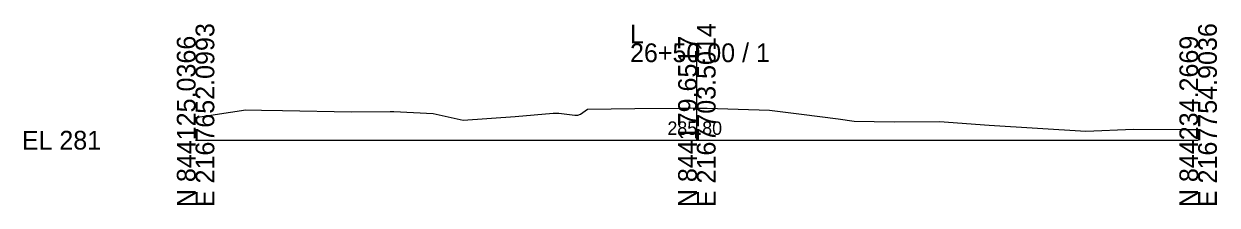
# Model space of a CAD drawing. Extents: x -26 to 1153, y -10 to 9544.
# Drawn here: x 974.3 to 1152.8, y 7990.3 to 8017.4 of the extents above; entities that cross this region are included whole.
import ezdxf

# ---------------------------------------------------------------- set-up
doc = ezdxf.new("R2010")
doc.units = 0
for name, color, linetype in [('Default', 7, 'Continuous'), ('Exist Cross Section Cell', 7, 'Continuous'), ('Exist XS Center Line Elevation Label', 7, 'Continuous'), ('Prop XS Earthwork Shape', 7, 'Continuous')]:
    doc.layers.add(name, color=color, linetype=linetype)

msp = doc.modelspace()

# ---------------------------------------------------------------- linework, layer by layer
at = {"layer": 'Exist Cross Section Cell'}
for p, q in [((1075, 8000), (1075, 8014.46)), ((1000, 8000), (1075, 8000)), ((1075, 8000), (1150, 8000))]:
    msp.add_line(p, q, dxfattribs=at)
at = {"layer": 'Prop XS Earthwork Shape'}
for p, q in [((1000, 8003.39), (1007.5, 8004.52)), ((1007.5, 8004.52), (1009.87, 8004.48)), ((1009.87, 8004.48), (1012.99, 8004.46)), ((1012.99, 8004.46), (1023.34, 8004.25)), ((1023.34, 8004.25), (1029.13, 8004.27)), ((1029.13, 8004.27), (1029.68, 8004.29)), ((1029.68, 8004.29), (1035.57, 8004.01)), ((1035.57, 8004.01), (1040.05, 8002.99)), ((1047.83, 8003.55), (1053.5, 8004.02)), ((1053.5, 8004.02), (1054.37, 8004.05)), ((1054.37, 8004.05), (1056.74, 8003.75)), ((1056.74, 8003.75), (1057.2, 8003.72)), ((1057.2, 8003.72), (1057.57, 8003.91)), ((1057.57, 8003.91), (1058.65, 8004.63)), ((1058.65, 8004.63), (1065.73, 8004.73)), ((1065.73, 8004.73), (1072.39, 8004.79)), ((1072.39, 8004.79), (1073.29, 8004.81)), ((1073.29, 8004.81), (1074.07, 8004.82)), ((1074.07, 8004.82), (1075.08, 8004.79)), ((1075.08, 8004.79), (1076.56, 8004.77)), ((1076.56, 8004.77), (1081.16, 8004.62)), ((1081.16, 8004.62), (1085.85, 8004.51)), ((1085.85, 8004.51), (1090.67, 8003.9)), ((1090.67, 8003.9), (1096.13, 8003.19)), ((1040.05, 8002.99), (1047.83, 8003.55)), ((1096.13, 8003.19), (1098.52, 8002.83)), ((1098.52, 8002.83), (1104.53, 8002.73)), ((1104.53, 8002.73), (1111.32, 8002.81)), ((1111.32, 8002.81), (1118.72, 8002.27)), ((1118.72, 8002.27), (1133.2, 8001.34)), ((1133.2, 8001.34), (1140.33, 8001.63)), ((1140.33, 8001.63), (1147.9, 8001.58)), ((1147.9, 8001.58), (1150, 8001.58))]:
    msp.add_line(p, q, dxfattribs=at)

# ---------------------------------------------------------------- texts
at = {"layer": 'Default'}
msp.add_text('-', height=0.0001, dxfattribs=at).set_placement((1000, 8000))
at = {"layer": 'Exist Cross Section Cell'}
for s, p in [('E 2167652.0993', (1002.8, 7990)), ('E 2167703.5014', (1077.8, 7990)), ('E 2167754.9036', (1152.8, 7990)), ('N 844125.0366', (1000, 7990)), ('N 844179.6517', (1075, 7990)), ('N 844234.2669', (1150, 7990))]:
    msp.add_text(s, height=2.8, rotation=90, dxfattribs=at).set_placement(p)
for s, p in [('L', (1065, 8014.46)), ('26+50.00 / 1', (1065, 8011.66)), ('EL 281', (974, 7998.6))]:
    msp.add_text(s, height=2.8, dxfattribs=at).set_placement(p)
at = {"layer": 'Exist XS Center Line Elevation Label'}
msp.add_text('285.80', height=2, dxfattribs=at).set_placement((1070.59, 8000.8))

doc.saveas('drawing.dxf')
